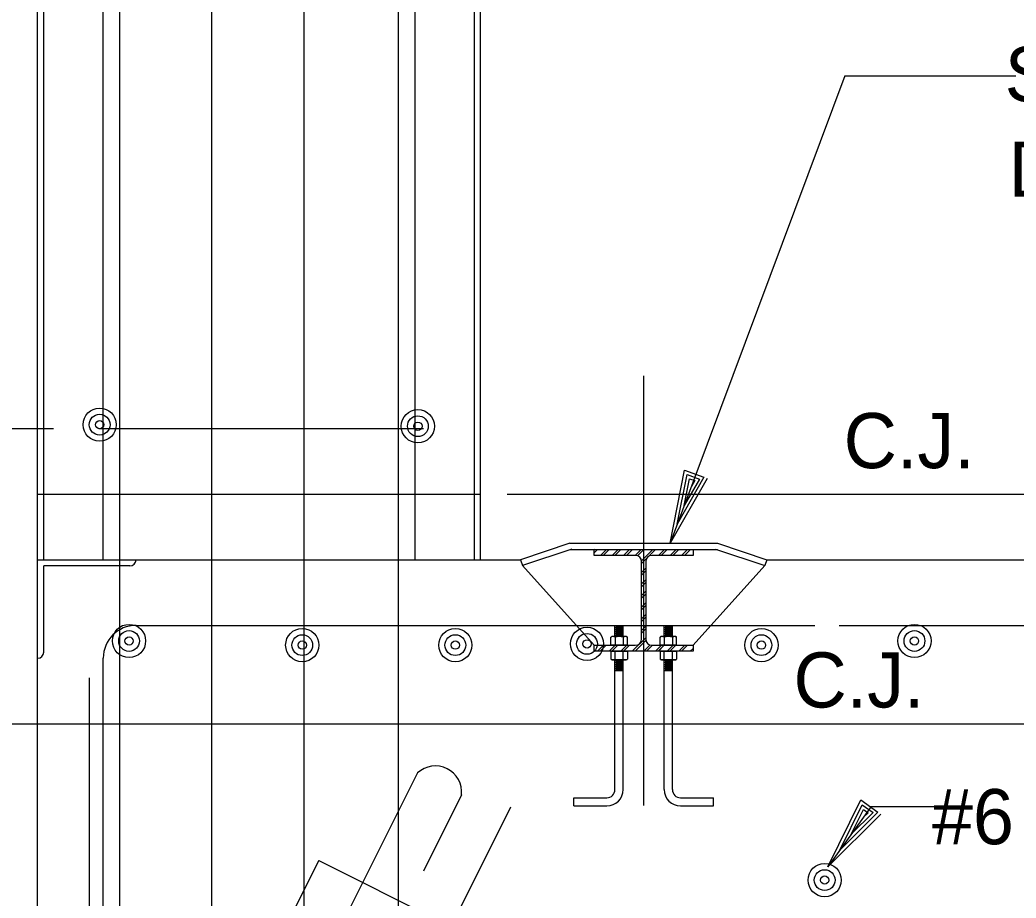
# Model space of a CAD drawing. Extents: x 6 to 106, y 3 to 74.
# Drawn here: x 84.18 to 90.92, y 57.35 to 63.29 of the extents above; entities that cross this region are included whole.
import ezdxf

# ---------------------------------------------------------------- set-up
doc = ezdxf.new("R2010")
doc.units = 0
for name, color, linetype in [('Level 13', 7, 'Continuous'), ('Level 22', 7, 'Continuous'), ('Level 36', 7, 'Continuous'), ('Level 50', 7, 'Continuous')]:
    doc.layers.add(name, color=color, linetype=linetype)

msp = doc.modelspace()

# ---------------------------------------------------------------- linework, layer by layer
at = {"layer": 'Level 13'}
for p, q in [((88.185, 59.1206), (88.1775, 59.1162)), ((88.1775, 59.0632), (88.1775, 59.1162)), ((88.2817, 59.1206), (88.185, 59.1206)), ((88.2054, 59.1163), (88.2054, 59.0632)), ((88.2613, 59.1163), (88.2613, 59.0632)), ((88.2817, 59.1206), (88.2891, 59.1162)), ((88.2891, 59.0632), (88.2891, 59.1162)), ((88.5183, 59.1206), (88.5108, 59.1162)), ((88.5108, 59.0632), (88.5108, 59.1162)), ((88.615, 59.1206), (88.5183, 59.1206)), ((88.5387, 59.1163), (88.5387, 59.0632)), ((88.5946, 59.1163), (88.5946, 59.0632)), ((88.615, 59.1206), (88.6224, 59.1162)), ((88.6224, 59.0632), (88.6224, 59.1162)), ((88.2891, 59.0632), (88.1775, 59.0632)), ((88.201, 59.0612), (88.201, 59.0632)), ((88.2656, 59.0612), (88.2656, 59.0632)), ((88.6224, 59.0632), (88.5108, 59.0632)), ((88.5343, 59.0612), (88.5343, 59.0632)), ((88.599, 59.0612), (88.599, 59.0632)), ((88.2891, 59.0199), (88.1775, 59.0199)), ((88.1775, 59.0199), (88.1775, 58.9669)), ((88.185, 58.9625), (88.1775, 58.9669)), ((88.2817, 58.9625), (88.185, 58.9625)), ((88.201, 59.0219), (88.201, 59.0199)), ((88.2054, 58.9668), (88.2054, 59.0199)), ((88.2613, 58.9668), (88.2613, 59.0199)), ((88.2656, 59.0219), (88.2656, 59.0199)), ((88.2817, 58.9625), (88.2891, 58.9669)), ((88.2891, 59.0199), (88.2891, 58.9669)), ((88.6224, 59.0199), (88.5108, 59.0199)), ((88.5108, 59.0199), (88.5108, 58.9669)), ((88.5183, 58.9625), (88.5108, 58.9669)), ((88.615, 58.9625), (88.5183, 58.9625)), ((88.5343, 59.0219), (88.5343, 59.0199)), ((88.5387, 58.9668), (88.5387, 59.0199)), ((88.5946, 58.9668), (88.5946, 59.0199)), ((88.599, 59.0219), (88.599, 59.0199)), ((88.615, 58.9625), (88.6224, 58.9669)), ((88.6224, 59.0199), (88.6224, 58.9669))]:
    msp.add_line(p, q, dxfattribs=at)
for centre, radius, start, end in [((88.1916, 59.0964), 0.0242, 55.48902, 120.28759), ((88.2337, 59.0236), 0.097, 73.50341, 106.98163), ((88.275, 59.0964), 0.0242, 59.71241, 124.51098), ((88.5249, 59.0964), 0.0242, 55.48902, 120.28759), ((88.567, 59.0236), 0.097, 73.50341, 106.98163), ((88.6083, 59.0964), 0.0242, 59.71241, 124.51098), ((88.1916, 58.9867), 0.0242, 239.71241, 304.51098), ((88.2337, 59.0595), 0.097, 253.01837, 286.49659), ((88.275, 58.9867), 0.0242, 235.48902, 300.28759), ((88.5249, 58.9867), 0.0242, 239.71241, 304.51098), ((88.567, 59.0595), 0.097, 253.01837, 286.49659), ((88.6083, 58.9867), 0.0242, 235.48902, 300.28759)]:
    msp.add_arc(centre, radius, start, end, dxfattribs=at)
at = {"layer": 'Level 22'}
for p, q in [((84.2951, 55.863), (84.2951, 68.974)), ((84.3368, 59.6407), (84.3368, 68.974)), ((84.7396, 59.6407), (84.7396, 68.974)), ((86.8507, 59.6407), (86.8507, 68.974)), ((87.2535, 59.6407), (87.2535, 68.974)), ((87.2951, 59.6407), (87.2951, 68.974)), ((85.4757, 56.994), (85.4757, 68.835)), ((86.1007, 56.9477), (86.1007, 68.835)), ((84.8507, 56.9477), (84.8507, 68.7628)), ((86.7396, 56.9227), (86.7396, 68.7772)), ((89.7616, 62.9166), (88.5783, 59.7518)), ((89.7616, 62.9166), (90.9202, 62.9166)), ((88.3993, 57.9769), (88.3993, 60.886)), ((80.2713, 60.5296), (84.4021, 60.5296)), ((84.7106, 60.5296), (86.9093, 60.5296)), ((84.2951, 60.0851), (87.2951, 60.0851)), ((87.4746, 60.0851), (98.1109, 60.0851)), ((87.8993, 59.7518), (87.566, 59.6407)), ((87.9125, 59.7123), (87.5791, 59.6012)), ((87.8993, 59.7518), (88.8993, 59.7518)), ((87.8993, 59.7101), (88.8993, 59.7101)), ((88.087, 59.7101), (88.0649, 59.688)), ((88.0685, 59.7101), (88.0649, 59.7065)), ((88.147, 59.7101), (88.1065, 59.6696)), ((88.1656, 59.7101), (88.125, 59.6696)), ((88.2256, 59.7101), (88.1851, 59.6696)), ((88.2441, 59.7101), (88.2036, 59.6696)), ((88.3042, 59.7101), (88.2636, 59.6696)), ((88.3227, 59.7101), (88.2821, 59.6696)), ((88.3827, 59.7101), (88.3422, 59.6696)), ((88.4013, 59.7101), (88.3574, 59.6663)), ((88.4613, 59.7101), (88.3839, 59.6327)), ((88.4798, 59.7101), (88.3848, 59.6152)), ((88.5399, 59.7101), (88.4993, 59.6696)), ((88.5584, 59.7101), (88.5178, 59.6696)), ((88.6184, 59.7101), (88.5779, 59.6696)), ((88.6369, 59.7101), (88.5964, 59.6696)), ((88.697, 59.7101), (88.6564, 59.6696)), ((88.7155, 59.7101), (88.6749, 59.6696)), ((88.8861, 59.7123), (89.2194, 59.6012)), ((88.8993, 59.7518), (89.2326, 59.6407)), ((84.2951, 59.6407), (87.566, 59.6407)), ((87.566, 59.6407), (87.5792, 59.6012)), ((89.2326, 59.6407), (89.2194, 59.6012)), ((89.2326, 59.6407), (94.9615, 59.6407)), ((84.3368, 59.0157), (84.3368, 59.599)), ((84.9201, 59.599), (84.3368, 59.599)), ((88.0649, 59.0618), (87.5791, 59.6012)), ((88.4137, 59.584), (88.3848, 59.5551)), ((88.7337, 59.0618), (89.2194, 59.6012)), ((88.4137, 59.5655), (88.3848, 59.5366)), ((88.4137, 59.5055), (88.3848, 59.4766)), ((88.4137, 59.4869), (88.3848, 59.4581)), ((88.4137, 59.4269), (88.3848, 59.398)), ((88.4137, 59.4084), (88.3848, 59.3795)), ((88.4137, 59.3483), (88.3848, 59.3194)), ((88.4137, 59.3298), (88.3848, 59.3009)), ((88.4137, 59.2698), (88.3848, 59.2409)), ((88.4137, 59.2512), (88.3848, 59.2224)), ((84.9618, 59.1963), (89.5589, 59.1963)), ((88.2049, 59.1963), (88.2604, 59.1963)), ((88.2049, 59.1206), (88.2049, 59.1963)), ((88.2049, 59.1824), (88.2604, 59.1824)), ((88.2049, 59.1685), (88.2604, 59.1685)), ((88.2118, 59.1893), (88.2535, 59.1893)), ((88.2118, 59.1754), (88.2535, 59.1754)), ((88.2604, 59.1206), (88.2604, 59.1963)), ((88.4137, 59.1912), (88.3848, 59.1623)), ((88.4137, 59.1727), (88.3848, 59.1438)), ((88.5382, 59.1963), (88.5937, 59.1963)), ((88.5382, 59.1963), (88.5937, 59.1963)), ((88.5382, 59.1206), (88.5382, 59.1963)), ((88.5382, 59.1824), (88.5937, 59.1824)), ((88.5382, 59.1685), (88.5937, 59.1685)), ((88.5451, 59.1893), (88.5868, 59.1893)), ((88.5451, 59.1754), (88.5868, 59.1754)), ((88.5937, 59.1206), (88.5937, 59.1963)), ((89.7223, 59.1963), (94.2949, 59.1963)), ((88.2049, 59.1546), (88.2604, 59.1546)), ((88.2049, 59.1407), (88.2604, 59.1407)), ((88.2049, 59.1268), (88.2604, 59.1268)), ((88.2118, 59.1616), (88.2535, 59.1616)), ((88.2118, 59.1477), (88.2535, 59.1477)), ((88.2118, 59.1338), (88.2535, 59.1338)), ((88.4137, 59.1126), (88.3224, 59.0213)), ((88.5382, 59.1546), (88.5937, 59.1546)), ((88.5382, 59.1407), (88.5937, 59.1407)), ((88.5382, 59.1268), (88.5937, 59.1268)), ((88.5451, 59.1616), (88.5868, 59.1616)), ((88.5451, 59.1477), (88.5868, 59.1477)), ((88.5451, 59.1338), (88.5868, 59.1338)), ((88.0672, 59.0618), (88.0649, 59.0595)), ((88.1272, 59.0618), (88.0867, 59.0213)), ((88.1458, 59.0618), (88.1052, 59.0213)), ((88.2058, 59.0618), (88.1653, 59.0213)), ((88.2243, 59.0618), (88.1838, 59.0213)), ((88.2844, 59.0618), (88.2438, 59.0213)), ((88.3029, 59.0618), (88.2623, 59.0213)), ((88.4152, 59.0956), (88.3409, 59.0213)), ((88.4437, 59.064), (88.4009, 59.0213)), ((88.46, 59.0618), (88.4195, 59.0213)), ((88.5201, 59.0618), (88.4795, 59.0213)), ((88.5386, 59.0618), (88.498, 59.0213)), ((88.5391, 59.0618), (88.4986, 59.0213)), ((88.5986, 59.0618), (88.5581, 59.0213)), ((88.6171, 59.0618), (88.5766, 59.0213)), ((88.6177, 59.0618), (88.5771, 59.0213)), ((88.6772, 59.0618), (88.6366, 59.0213)), ((88.6957, 59.0618), (88.6552, 59.0213)), ((88.7337, 59.0398), (88.7152, 59.0213)), ((84.7396, 57.2881), (84.7396, 58.9741)), ((88.2049, 58.0852), (88.2049, 58.9625)), ((88.2604, 58.0852), (88.2604, 58.9625)), ((88.5382, 58.0852), (88.5382, 58.9625)), ((88.5937, 58.0852), (88.5937, 58.9625)), ((88.7337, 59.0213), (88.7337, 59.0213)), ((88.2049, 58.9602), (88.2604, 58.9602)), ((88.2049, 58.9463), (88.2604, 58.9463)), ((88.2049, 58.9324), (88.2604, 58.9324)), ((88.2049, 58.9185), (88.2604, 58.9185)), ((88.2049, 58.9046), (88.2604, 58.9046)), ((88.2118, 58.9532), (88.2535, 58.9532)), ((88.2118, 58.9393), (88.2535, 58.9393)), ((88.2118, 58.9254), (88.2535, 58.9254)), ((88.2118, 58.9116), (88.2535, 58.9116)), ((88.2118, 58.8977), (88.2535, 58.8977)), ((88.5382, 58.9602), (88.5937, 58.9602)), ((88.5382, 58.9463), (88.5937, 58.9463)), ((88.5382, 58.9324), (88.5937, 58.9324)), ((88.5382, 58.9185), (88.5937, 58.9185)), ((88.5382, 58.9046), (88.5937, 58.9046)), ((88.5451, 58.9532), (88.5868, 58.9532)), ((88.5451, 58.9393), (88.5868, 58.9393)), ((88.5451, 58.9254), (88.5868, 58.9254)), ((88.5451, 58.9116), (88.5868, 58.9116)), ((88.5451, 58.8977), (88.5868, 58.8977)), ((84.6469, 56.9741), (84.6469, 58.8421)), ((88.2049, 58.8907), (88.2604, 58.8907)), ((88.5382, 58.8907), (88.5937, 58.8907)), ((80.4983, 58.5296), (84.2951, 58.5296)), ((84.2951, 58.5296), (94.9615, 58.5296)), ((86.8676, 58.1978), (83.4296, 51.3218)), ((87.1657, 58.0487), (86.9081, 57.5334)), ((87.9271, 57.9741), (87.9271, 58.0296)), ((87.9271, 58.0296), (88.1493, 58.0296)), ((88.6493, 58.0296), (88.8715, 58.0296)), ((88.8715, 57.9741), (88.8715, 58.0296)), ((87.4966, 57.9651), (84.0258, 51.0237)), ((87.9271, 57.9741), (88.1493, 57.9741)), ((88.6493, 57.9741), (88.8715, 57.9741)), ((89.9398, 57.9703), (89.6462, 57.5624)), ((89.9398, 57.9703), (90.3908, 57.9703)), ((86.1988, 57.6056), (83.1314, 51.4709)), ((86.1988, 57.6056), (87.3913, 57.0093))]:
    msp.add_line(p, q, dxfattribs=at)
for centre, radius, start, end in [((84.9201, 59.6407), 0.0417, 270, 0), ((84.9618, 58.9741), 0.2222, 90, 180), ((84.2951, 59.0157), 0.0417, 270, 0), ((86.9886, 58.0672), 0.178, 354.02638, 132.83925), ((88.1493, 58.0852), 0.0556, 270, 0), ((88.1493, 58.0852), 0.1111, 270, 0), ((88.6493, 58.0852), 0.1111, 180, 270), ((88.6493, 58.0852), 0.0556, 180, 270)]:
    msp.add_arc(centre, radius, start, end, dxfattribs=at)
at = {"layer": 'Level 36'}
for p, q in [((88.0649, 59.6696), (88.0649, 59.7101)), ((88.0649, 59.7101), (88.7337, 59.7101)), ((88.7337, 59.7101), (88.7337, 59.6696)), ((88.3421, 59.6696), (88.0649, 59.6696)), ((88.7337, 59.6696), (88.4565, 59.6696)), ((88.3848, 59.1046), (88.3848, 59.6268)), ((88.4137, 59.6268), (88.4137, 59.1046)), ((88.0649, 59.0213), (88.0649, 59.0618)), ((88.0649, 59.0618), (88.3421, 59.0618)), ((88.4565, 59.0618), (88.7337, 59.0618)), ((88.7337, 59.0618), (88.7337, 59.0213)), ((88.7337, 59.0213), (88.0649, 59.0213))]:
    msp.add_line(p, q, dxfattribs=at)
for centre, start, end in [((88.3421, 59.6268), 0, 90), ((88.4565, 59.6268), 90, 180), ((88.3421, 59.1046), 270, 0), ((88.4565, 59.1046), 180, 270)]:
    msp.add_arc(centre, 0.0428, start, end, dxfattribs=at)
at = {"layer": 'Level 50'}
for p, q in [((88.6268, 59.8817), (88.6268, 59.8817)), ((88.5783, 59.7518), (88.5783, 59.7518)), ((89.7272, 57.6749), (89.7272, 57.6749)), ((89.6462, 57.5624), (89.6462, 57.5624))]:
    msp.add_line(p, q, dxfattribs=at)
for points in [[(88.8303, 60.1899), (88.5783, 59.7518), (88.6755, 60.2479), (88.8078, 60.1984), (88.6268, 59.8817), (88.693, 60.2185), (88.7779, 60.1868), (88.6735, 60.0066), (88.7105, 60.1892), (88.7454, 60.1761), (88.7221, 60.1365)], [(90.0046, 57.9188), (89.6462, 57.5624), (89.8704, 58.0154), (89.9851, 57.9329), (89.7272, 57.6749), (89.8796, 57.9825), (89.9532, 57.9296), (89.8051, 57.7832), (89.8888, 57.9496), (89.9191, 57.9278), (89.8861, 57.8957)]]:
    msp.add_lwpolyline(points, dxfattribs=at)
for centre, radius in [((84.7151, 60.5548), 0.1125), ((86.8702, 60.5443), 0.1125), ((84.7151, 60.5548), 0.0703), ((84.7151, 60.5548), 0.0281), ((86.8702, 60.5443), 0.0703), ((86.8702, 60.5443), 0.0281), ((84.9142, 59.0908), 0.1125), ((86.0873, 59.0627), 0.1125), ((87.1238, 59.0627), 0.1125), ((88.0155, 59.0709), 0.1125), ((89.1967, 59.0627), 0.1125), ((90.2331, 59.0908), 0.1125), ((84.9142, 59.0908), 0.0703), ((84.9142, 59.0908), 0.0281), ((86.0873, 59.0627), 0.0703), ((87.1238, 59.0627), 0.0703), ((88.0155, 59.0709), 0.0703), ((88.0155, 59.0709), 0.0281), ((89.1967, 59.0627), 0.0703), ((90.2331, 59.0908), 0.0703), ((90.2331, 59.0908), 0.0281), ((86.0873, 59.0627), 0.0281), ((87.1238, 59.0627), 0.0281), ((89.1967, 59.0627), 0.0281), ((89.625, 57.4725), 0.1125), ((89.625, 57.4725), 0.0703), ((89.625, 57.4725), 0.0281)]:
    msp.add_circle(centre, radius, dxfattribs=at)

# ---------------------------------------------------------------- texts
at = {"layer": 'Level 22'}
for s, height, p in [('SEAL PL. SEE DETAIL', 0.373333, (90.8444, 62.7411)), ('DWG. 32.', 0.37333, (90.8716, 62.0981)), ('C.J.', 0.37333, (89.7538, 60.2603)), ('C.J.', 0.37333, (89.4139, 58.6404)), ('#6', 0.37333, (90.3513, 57.7148))]:
    msp.add_text(s, height=height, dxfattribs=at).set_placement(p)

doc.saveas('drawing.dxf')
